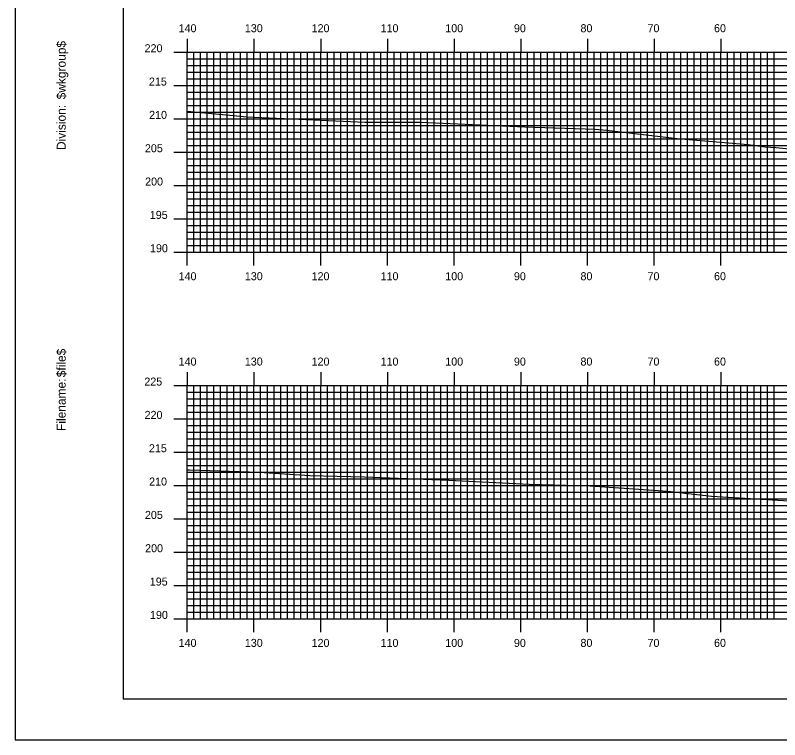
# Model space of a CAD drawing. Extents: x 1805864 to 1806208, y 442591 to 442811.
# Drawn here: x 1805864.4 to 1805979, y 442590.5 to 442699.2 of the extents above; entities that cross this region are included whole.
import ezdxf

# ---------------------------------------------------------------- set-up
doc = ezdxf.new("R2010")
doc.units = 0
for name, color, linetype in [('BORDER', 7, 'Continuous'), ('H_V ANNOTATION', 7, 'Continuous'), ('MAJOR', 7, 'Continuous'), ('MINOR', 7, 'Continuous'), ('PLOT BOUNDARY', 7, 'Continuous'), ('S_Roadway_Centerline', 7, 'Continuous')]:
    doc.layers.add(name, color=color, linetype=linetype)

msp = doc.modelspace()

# ---------------------------------------------------------------- linework, layer by layer
at = {"layer": 'BORDER'}
msp.add_lwpolyline([(1805880.62, 442596.67), (1806200.62, 442596.67), (1806200.62, 442806.67), (1805880.62, 442806.67)], close=True, dxfattribs=at)
at = {"layer": 'MAJOR'}
for p, q in [((1805890.22, 442695.67), (1805890.22, 442693.67)), ((1805900.22, 442695.67), (1805900.22, 442693.67)), ((1805910.22, 442695.67), (1805910.22, 442693.67)), ((1805920.22, 442695.67), (1805920.22, 442693.67)), ((1805930.22, 442695.67), (1805930.22, 442693.67)), ((1805940.22, 442695.67), (1805940.22, 442693.67)), ((1805950.22, 442695.67), (1805950.22, 442693.67)), ((1805960.22, 442695.67), (1805960.22, 442693.67)), ((1805970.22, 442695.67), (1805970.22, 442693.67)), ((1805888.22, 442693.67), (1805890.22, 442693.67)), ((1805890.22, 442693.67), (1806170.22, 442693.67)), ((1805890.22, 442663.67), (1805890.22, 442693.67)), ((1805890.22, 442663.67), (1805890.22, 442693.67)), ((1805890.22, 442693.67), (1806170.22, 442693.67)), ((1805900.22, 442663.67), (1805900.22, 442693.67)), ((1805910.22, 442663.67), (1805910.22, 442693.67)), ((1805920.22, 442663.67), (1805920.22, 442693.67)), ((1805930.22, 442663.67), (1805930.22, 442693.67)), ((1805940.22, 442663.67), (1805940.22, 442693.67)), ((1805950.22, 442663.67), (1805950.22, 442693.67)), ((1805960.22, 442663.67), (1805960.22, 442693.67)), ((1805970.22, 442663.67), (1805970.22, 442693.67)), ((1805888.22, 442688.67), (1805890.22, 442688.67)), ((1805890.22, 442688.67), (1806170.22, 442688.67)), ((1805888.22, 442683.67), (1805890.22, 442683.67)), ((1805890.22, 442683.67), (1806170.22, 442683.67)), ((1805888.22, 442678.67), (1805890.22, 442678.67)), ((1805890.22, 442678.67), (1806170.22, 442678.67)), ((1805888.22, 442673.67), (1805890.22, 442673.67)), ((1805890.22, 442673.67), (1806170.22, 442673.67)), ((1805888.22, 442668.67), (1805890.22, 442668.67)), ((1805890.22, 442668.67), (1806170.22, 442668.67)), ((1805888.22, 442663.67), (1805890.22, 442663.67)), ((1805890.22, 442663.67), (1806170.22, 442663.67)), ((1805890.22, 442663.67), (1806170.22, 442663.67)), ((1805890.22, 442661.66), (1805890.22, 442663.67)), ((1805900.22, 442661.66), (1805900.22, 442663.67)), ((1805910.22, 442661.66), (1805910.22, 442663.67)), ((1805920.22, 442661.66), (1805920.22, 442663.67)), ((1805930.22, 442661.66), (1805930.22, 442663.67)), ((1805940.22, 442661.66), (1805940.22, 442663.67)), ((1805950.22, 442661.66), (1805950.22, 442663.67)), ((1805960.22, 442661.66), (1805960.22, 442663.67)), ((1805970.22, 442661.66), (1805970.22, 442663.67)), ((1805890.22, 442645.67), (1805890.22, 442643.67)), ((1805900.22, 442645.67), (1805900.22, 442643.67)), ((1805910.22, 442645.67), (1805910.22, 442643.67)), ((1805920.22, 442645.67), (1805920.22, 442643.67)), ((1805930.22, 442645.67), (1805930.22, 442643.67)), ((1805940.22, 442645.67), (1805940.22, 442643.67)), ((1805950.22, 442645.67), (1805950.22, 442643.67)), ((1805960.22, 442645.67), (1805960.22, 442643.67)), ((1805970.22, 442645.67), (1805970.22, 442643.67)), ((1805888.22, 442643.67), (1805890.22, 442643.67)), ((1805890.22, 442643.67), (1806170.22, 442643.67)), ((1805890.22, 442608.67), (1805890.22, 442643.67)), ((1805890.22, 442608.67), (1805890.22, 442643.67)), ((1805890.22, 442643.67), (1806170.22, 442643.67)), ((1805900.22, 442608.67), (1805900.22, 442643.67)), ((1805910.22, 442608.67), (1805910.22, 442643.67)), ((1805920.22, 442608.67), (1805920.22, 442643.67)), ((1805930.22, 442608.67), (1805930.22, 442643.67)), ((1805940.22, 442608.67), (1805940.22, 442643.67)), ((1805950.22, 442608.67), (1805950.22, 442643.67)), ((1805960.22, 442608.67), (1805960.22, 442643.67)), ((1805970.22, 442608.67), (1805970.22, 442643.67)), ((1805888.22, 442638.67), (1805890.22, 442638.67)), ((1805890.22, 442638.67), (1806170.22, 442638.67)), ((1805888.22, 442633.67), (1805890.22, 442633.67)), ((1805890.22, 442633.67), (1806170.22, 442633.67)), ((1805888.22, 442628.67), (1805890.22, 442628.67)), ((1805890.22, 442628.67), (1806170.22, 442628.67)), ((1805888.22, 442623.67), (1805890.22, 442623.67)), ((1805890.22, 442623.67), (1806170.22, 442623.67)), ((1805888.22, 442618.67), (1805890.22, 442618.67)), ((1805890.22, 442618.67), (1806170.22, 442618.67)), ((1805888.22, 442613.67), (1805890.22, 442613.67)), ((1805890.22, 442613.67), (1806170.22, 442613.67)), ((1805888.22, 442608.67), (1805890.22, 442608.67)), ((1805890.22, 442608.67), (1806170.22, 442608.67)), ((1805890.22, 442608.67), (1806170.22, 442608.67)), ((1805890.22, 442606.66), (1805890.22, 442608.67)), ((1805900.22, 442606.66), (1805900.22, 442608.67)), ((1805910.22, 442606.66), (1805910.22, 442608.67)), ((1805920.22, 442606.66), (1805920.22, 442608.67)), ((1805930.22, 442606.66), (1805930.22, 442608.67)), ((1805940.22, 442606.66), (1805940.22, 442608.67)), ((1805950.22, 442606.66), (1805950.22, 442608.67)), ((1805960.22, 442606.66), (1805960.22, 442608.67)), ((1805970.22, 442606.66), (1805970.22, 442608.67))]:
    msp.add_line(p, q, dxfattribs=at)
at = {"layer": 'MINOR'}
for p, q in [((1805891.22, 442663.67), (1805891.22, 442693.67)), ((1805892.22, 442663.67), (1805892.22, 442693.67)), ((1805893.22, 442663.67), (1805893.22, 442693.67)), ((1805894.22, 442663.67), (1805894.22, 442693.67)), ((1805895.22, 442663.67), (1805895.22, 442693.67)), ((1805896.22, 442663.67), (1805896.22, 442693.67)), ((1805897.22, 442663.67), (1805897.22, 442693.67)), ((1805898.22, 442663.67), (1805898.22, 442693.67)), ((1805899.22, 442663.67), (1805899.22, 442693.67)), ((1805901.22, 442663.67), (1805901.22, 442693.67)), ((1805902.22, 442663.67), (1805902.22, 442693.67)), ((1805903.22, 442663.67), (1805903.22, 442693.67)), ((1805904.22, 442663.67), (1805904.22, 442693.67)), ((1805905.22, 442663.67), (1805905.22, 442693.67)), ((1805906.22, 442663.67), (1805906.22, 442693.67)), ((1805907.22, 442663.67), (1805907.22, 442693.67)), ((1805908.22, 442663.67), (1805908.22, 442693.67)), ((1805909.22, 442663.67), (1805909.22, 442693.67)), ((1805911.22, 442663.67), (1805911.22, 442693.67)), ((1805912.22, 442663.67), (1805912.22, 442693.67)), ((1805913.22, 442663.67), (1805913.22, 442693.67)), ((1805914.22, 442663.67), (1805914.22, 442693.67)), ((1805915.22, 442663.67), (1805915.22, 442693.67)), ((1805916.22, 442663.67), (1805916.22, 442693.67)), ((1805917.22, 442663.67), (1805917.22, 442693.67)), ((1805918.22, 442663.67), (1805918.22, 442693.67)), ((1805919.22, 442663.67), (1805919.22, 442693.67)), ((1805921.22, 442663.67), (1805921.22, 442693.67)), ((1805922.22, 442663.67), (1805922.22, 442693.67)), ((1805923.22, 442663.67), (1805923.22, 442693.67)), ((1805924.22, 442663.67), (1805924.22, 442693.67)), ((1805925.22, 442663.67), (1805925.22, 442693.67)), ((1805926.22, 442663.67), (1805926.22, 442693.67)), ((1805927.22, 442663.67), (1805927.22, 442693.67)), ((1805928.22, 442663.67), (1805928.22, 442693.67)), ((1805929.22, 442663.67), (1805929.22, 442693.67)), ((1805931.22, 442663.67), (1805931.22, 442693.67)), ((1805932.22, 442663.67), (1805932.22, 442693.67)), ((1805933.22, 442663.67), (1805933.22, 442693.67)), ((1805934.22, 442663.67), (1805934.22, 442693.67)), ((1805935.22, 442663.67), (1805935.22, 442693.67)), ((1805936.22, 442663.67), (1805936.22, 442693.67)), ((1805937.22, 442663.67), (1805937.22, 442693.67)), ((1805938.22, 442663.67), (1805938.22, 442693.67)), ((1805939.22, 442663.67), (1805939.22, 442693.67)), ((1805941.22, 442663.67), (1805941.22, 442693.67)), ((1805942.22, 442663.67), (1805942.22, 442693.67)), ((1805943.22, 442663.67), (1805943.22, 442693.67)), ((1805944.22, 442663.67), (1805944.22, 442693.67)), ((1805945.22, 442663.67), (1805945.22, 442693.67)), ((1805946.22, 442663.67), (1805946.22, 442693.67)), ((1805947.22, 442663.67), (1805947.22, 442693.67)), ((1805948.22, 442663.67), (1805948.22, 442693.67)), ((1805949.22, 442663.67), (1805949.22, 442693.67)), ((1805951.22, 442663.67), (1805951.22, 442693.67)), ((1805952.22, 442663.67), (1805952.22, 442693.67)), ((1805953.22, 442663.67), (1805953.22, 442693.67)), ((1805954.22, 442663.67), (1805954.22, 442693.67)), ((1805955.22, 442663.67), (1805955.22, 442693.67)), ((1805956.22, 442663.67), (1805956.22, 442693.67)), ((1805957.22, 442663.67), (1805957.22, 442693.67)), ((1805958.22, 442663.67), (1805958.22, 442693.67)), ((1805959.22, 442663.67), (1805959.22, 442693.67)), ((1805961.22, 442663.67), (1805961.22, 442693.67)), ((1805962.22, 442663.67), (1805962.22, 442693.67)), ((1805963.22, 442663.67), (1805963.22, 442693.67)), ((1805964.22, 442663.67), (1805964.22, 442693.67)), ((1805965.22, 442663.67), (1805965.22, 442693.67)), ((1805966.22, 442663.67), (1805966.22, 442693.67)), ((1805967.22, 442663.67), (1805967.22, 442693.67)), ((1805968.22, 442663.67), (1805968.22, 442693.67)), ((1805969.22, 442663.67), (1805969.22, 442693.67)), ((1805971.22, 442663.67), (1805971.22, 442693.67)), ((1805972.22, 442663.67), (1805972.22, 442693.67)), ((1805973.22, 442663.67), (1805973.22, 442693.67)), ((1805974.22, 442663.67), (1805974.22, 442693.67)), ((1805975.22, 442663.67), (1805975.22, 442693.67)), ((1805976.22, 442663.67), (1805976.22, 442693.67)), ((1805977.22, 442663.67), (1805977.22, 442693.67)), ((1805978.22, 442663.67), (1805978.22, 442693.67)), ((1805890.22, 442692.67), (1806170.22, 442692.67)), ((1805890.22, 442692.67), (1805892.22, 442692.67)), ((1805890.22, 442691.67), (1806170.22, 442691.67)), ((1805890.22, 442691.67), (1805892.22, 442691.67)), ((1805890.22, 442690.67), (1806170.22, 442690.67)), ((1805890.22, 442690.67), (1805892.22, 442690.67)), ((1805890.22, 442689.67), (1806170.22, 442689.67)), ((1805890.22, 442689.67), (1805892.22, 442689.67)), ((1805890.22, 442687.67), (1806170.22, 442687.67)), ((1805890.22, 442687.67), (1805892.22, 442687.67)), ((1805890.22, 442686.67), (1806170.22, 442686.67)), ((1805890.22, 442686.67), (1805892.22, 442686.67)), ((1805890.22, 442685.67), (1806170.22, 442685.67)), ((1805890.22, 442685.67), (1805892.22, 442685.67)), ((1805890.22, 442684.67), (1806170.22, 442684.67)), ((1805890.22, 442684.67), (1805892.22, 442684.67)), ((1805890.22, 442682.67), (1806170.22, 442682.67)), ((1805890.22, 442682.67), (1805892.22, 442682.67)), ((1805890.22, 442681.67), (1806170.22, 442681.67)), ((1805890.22, 442681.67), (1805892.22, 442681.67)), ((1805890.22, 442680.67), (1806170.22, 442680.67)), ((1805890.22, 442680.67), (1805892.22, 442680.67)), ((1805890.22, 442679.67), (1806170.22, 442679.67)), ((1805890.22, 442679.67), (1805892.22, 442679.67)), ((1805890.22, 442677.67), (1806170.22, 442677.67)), ((1805890.22, 442677.67), (1805892.22, 442677.67)), ((1805890.22, 442676.67), (1806170.22, 442676.67)), ((1805890.22, 442676.67), (1805892.22, 442676.67)), ((1805890.22, 442675.67), (1806170.22, 442675.67)), ((1805890.22, 442675.67), (1805892.22, 442675.67)), ((1805890.22, 442674.67), (1806170.22, 442674.67)), ((1805890.22, 442674.67), (1805892.22, 442674.67)), ((1805890.22, 442672.67), (1806170.22, 442672.67)), ((1805890.22, 442672.67), (1805892.22, 442672.67)), ((1805890.22, 442671.67), (1806170.22, 442671.67)), ((1805890.22, 442671.67), (1805892.22, 442671.67)), ((1805890.22, 442670.67), (1806170.22, 442670.67)), ((1805890.22, 442670.67), (1805892.22, 442670.67)), ((1805890.22, 442669.67), (1806170.22, 442669.67)), ((1805890.22, 442669.67), (1805892.22, 442669.67)), ((1805890.22, 442667.67), (1806170.22, 442667.67)), ((1805890.22, 442667.67), (1805892.22, 442667.67)), ((1805890.22, 442666.67), (1806170.22, 442666.67)), ((1805890.22, 442666.67), (1805892.22, 442666.67)), ((1805890.22, 442665.67), (1806170.22, 442665.67)), ((1805890.22, 442665.67), (1805892.22, 442665.67)), ((1805890.22, 442664.67), (1806170.22, 442664.67)), ((1805890.22, 442664.67), (1805892.22, 442664.67)), ((1805891.22, 442608.67), (1805891.22, 442643.67)), ((1805892.22, 442608.67), (1805892.22, 442643.67)), ((1805893.22, 442608.67), (1805893.22, 442643.67)), ((1805894.22, 442608.67), (1805894.22, 442643.67)), ((1805895.22, 442608.67), (1805895.22, 442643.67)), ((1805896.22, 442608.67), (1805896.22, 442643.67)), ((1805897.22, 442608.67), (1805897.22, 442643.67)), ((1805898.22, 442608.67), (1805898.22, 442643.67)), ((1805899.22, 442608.67), (1805899.22, 442643.67)), ((1805901.22, 442608.67), (1805901.22, 442643.67)), ((1805902.22, 442608.67), (1805902.22, 442643.67)), ((1805903.22, 442608.67), (1805903.22, 442643.67)), ((1805904.22, 442608.67), (1805904.22, 442643.67)), ((1805905.22, 442608.67), (1805905.22, 442643.67)), ((1805906.22, 442608.67), (1805906.22, 442643.67)), ((1805907.22, 442608.67), (1805907.22, 442643.67)), ((1805908.22, 442608.67), (1805908.22, 442643.67)), ((1805909.22, 442608.67), (1805909.22, 442643.67)), ((1805911.22, 442608.67), (1805911.22, 442643.67)), ((1805912.22, 442608.67), (1805912.22, 442643.67)), ((1805913.22, 442608.67), (1805913.22, 442643.67)), ((1805914.22, 442608.67), (1805914.22, 442643.67)), ((1805915.22, 442608.67), (1805915.22, 442643.67)), ((1805916.22, 442608.67), (1805916.22, 442643.67)), ((1805917.22, 442608.67), (1805917.22, 442643.67)), ((1805918.22, 442608.67), (1805918.22, 442643.67)), ((1805919.22, 442608.67), (1805919.22, 442643.67)), ((1805921.22, 442608.67), (1805921.22, 442643.67)), ((1805922.22, 442608.67), (1805922.22, 442643.67)), ((1805923.22, 442608.67), (1805923.22, 442643.67)), ((1805924.22, 442608.67), (1805924.22, 442643.67)), ((1805925.22, 442608.67), (1805925.22, 442643.67)), ((1805926.22, 442608.67), (1805926.22, 442643.67)), ((1805927.22, 442608.67), (1805927.22, 442643.67)), ((1805928.22, 442608.67), (1805928.22, 442643.67)), ((1805929.22, 442608.67), (1805929.22, 442643.67)), ((1805931.22, 442608.67), (1805931.22, 442643.67)), ((1805932.22, 442608.67), (1805932.22, 442643.67)), ((1805933.22, 442608.67), (1805933.22, 442643.67)), ((1805934.22, 442608.67), (1805934.22, 442643.67)), ((1805935.22, 442608.67), (1805935.22, 442643.67)), ((1805936.22, 442608.67), (1805936.22, 442643.67)), ((1805937.22, 442608.67), (1805937.22, 442643.67)), ((1805938.22, 442608.67), (1805938.22, 442643.67)), ((1805939.22, 442608.67), (1805939.22, 442643.67)), ((1805941.22, 442608.67), (1805941.22, 442643.67)), ((1805942.22, 442608.67), (1805942.22, 442643.67)), ((1805943.22, 442608.67), (1805943.22, 442643.67)), ((1805944.22, 442608.67), (1805944.22, 442643.67)), ((1805945.22, 442608.67), (1805945.22, 442643.67)), ((1805946.22, 442608.67), (1805946.22, 442643.67)), ((1805947.22, 442608.67), (1805947.22, 442643.67)), ((1805948.22, 442608.67), (1805948.22, 442643.67)), ((1805949.22, 442608.67), (1805949.22, 442643.67)), ((1805951.22, 442608.67), (1805951.22, 442643.67)), ((1805952.22, 442608.67), (1805952.22, 442643.67)), ((1805953.22, 442608.67), (1805953.22, 442643.67)), ((1805954.22, 442608.67), (1805954.22, 442643.67)), ((1805955.22, 442608.67), (1805955.22, 442643.67)), ((1805956.22, 442608.67), (1805956.22, 442643.67)), ((1805957.22, 442608.67), (1805957.22, 442643.67)), ((1805958.22, 442608.67), (1805958.22, 442643.67)), ((1805959.22, 442608.67), (1805959.22, 442643.67)), ((1805961.22, 442608.67), (1805961.22, 442643.67)), ((1805962.22, 442608.67), (1805962.22, 442643.67)), ((1805963.22, 442608.67), (1805963.22, 442643.67)), ((1805964.22, 442608.67), (1805964.22, 442643.67)), ((1805965.22, 442608.67), (1805965.22, 442643.67)), ((1805966.22, 442608.67), (1805966.22, 442643.67)), ((1805967.22, 442608.67), (1805967.22, 442643.67)), ((1805968.22, 442608.67), (1805968.22, 442643.67)), ((1805969.22, 442608.67), (1805969.22, 442643.67)), ((1805971.22, 442608.67), (1805971.22, 442643.67)), ((1805972.22, 442608.67), (1805972.22, 442643.67)), ((1805973.22, 442608.67), (1805973.22, 442643.67)), ((1805974.22, 442608.67), (1805974.22, 442643.67)), ((1805975.22, 442608.67), (1805975.22, 442643.67)), ((1805976.22, 442608.67), (1805976.22, 442643.67)), ((1805977.22, 442608.67), (1805977.22, 442643.67)), ((1805978.22, 442608.67), (1805978.22, 442643.67)), ((1805890.22, 442642.67), (1806170.22, 442642.67)), ((1805890.22, 442642.67), (1805892.22, 442642.67)), ((1805890.22, 442641.67), (1806170.22, 442641.67)), ((1805890.22, 442641.67), (1805892.22, 442641.67)), ((1805890.22, 442640.67), (1806170.22, 442640.67)), ((1805890.22, 442640.67), (1805892.22, 442640.67)), ((1805890.22, 442639.67), (1806170.22, 442639.67)), ((1805890.22, 442639.67), (1805892.22, 442639.67)), ((1805890.22, 442637.67), (1806170.22, 442637.67)), ((1805890.22, 442637.67), (1805892.22, 442637.67)), ((1805890.22, 442636.67), (1806170.22, 442636.67)), ((1805890.22, 442636.67), (1805892.22, 442636.67)), ((1805890.22, 442635.67), (1806170.22, 442635.67)), ((1805890.22, 442635.67), (1805892.22, 442635.67)), ((1805890.22, 442634.67), (1806170.22, 442634.67)), ((1805890.22, 442634.67), (1805892.22, 442634.67)), ((1805890.22, 442632.67), (1806170.22, 442632.67)), ((1805890.22, 442632.67), (1805892.22, 442632.67)), ((1805890.22, 442631.67), (1806170.22, 442631.67)), ((1805890.22, 442631.67), (1805892.22, 442631.67)), ((1805890.22, 442630.67), (1806170.22, 442630.67)), ((1805890.22, 442630.67), (1805892.22, 442630.67)), ((1805890.22, 442629.67), (1806170.22, 442629.67)), ((1805890.22, 442629.67), (1805892.22, 442629.67)), ((1805890.22, 442627.67), (1806170.22, 442627.67)), ((1805890.22, 442627.67), (1805892.22, 442627.67)), ((1805890.22, 442626.67), (1806170.22, 442626.67)), ((1805890.22, 442626.67), (1805892.22, 442626.67)), ((1805890.22, 442625.67), (1806170.22, 442625.67)), ((1805890.22, 442625.67), (1805892.22, 442625.67)), ((1805890.22, 442624.67), (1806170.22, 442624.67)), ((1805890.22, 442624.67), (1805892.22, 442624.67)), ((1805890.22, 442622.67), (1806170.22, 442622.67)), ((1805890.22, 442622.67), (1805892.22, 442622.67)), ((1805890.22, 442621.67), (1806170.22, 442621.67)), ((1805890.22, 442621.67), (1805892.22, 442621.67)), ((1805890.22, 442620.67), (1806170.22, 442620.67)), ((1805890.22, 442620.67), (1805892.22, 442620.67)), ((1805890.22, 442619.67), (1806170.22, 442619.67)), ((1805890.22, 442619.67), (1805892.22, 442619.67)), ((1805890.22, 442617.67), (1806170.22, 442617.67)), ((1805890.22, 442617.67), (1805892.22, 442617.67)), ((1805890.22, 442616.67), (1806170.22, 442616.67)), ((1805890.22, 442616.67), (1805892.22, 442616.67)), ((1805890.22, 442615.67), (1806170.22, 442615.67)), ((1805890.22, 442615.67), (1805892.22, 442615.67)), ((1805890.22, 442614.67), (1806170.22, 442614.67)), ((1805890.22, 442614.67), (1805892.22, 442614.67)), ((1805890.22, 442612.67), (1806170.22, 442612.67)), ((1805890.22, 442612.67), (1805892.22, 442612.67)), ((1805890.22, 442611.67), (1806170.22, 442611.67)), ((1805890.22, 442611.67), (1805892.22, 442611.67)), ((1805890.22, 442610.67), (1806170.22, 442610.67)), ((1805890.22, 442610.67), (1805892.22, 442610.67)), ((1805890.22, 442609.67), (1806170.22, 442609.67)), ((1805890.22, 442609.67), (1805892.22, 442609.67))]:
    msp.add_line(p, q, dxfattribs=at)
at = {"layer": 'PLOT BOUNDARY'}
msp.add_lwpolyline([(1805864.43, 442590.55), (1806204.43, 442590.55), (1806204.43, 442810.55), (1805864.43, 442810.55)], close=True, dxfattribs=at)
at = {"layer": 'S_Roadway_Centerline'}
for points in [[(1805890.22, 442684.81), (1805899.22, 442683.99), (1805916.89, 442683.2), (1805925.19, 442683.16), (1805940.8, 442682.48), (1805951.36, 442682.13), (1805953.07, 442681.97), (1805963.64, 442680.71), (1805974.31, 442679.81), (1805976.84, 442679.49), (1805978.48, 442679.38), (1805999.99, 442677.25)], [(1805890.22, 442631.03), (1805890.57, 442631.03), (1805901, 442630.66), (1805908.6, 442630.2), (1805916.78, 442629.96), (1805929.43, 442629.47), (1805941.49, 442628.87), (1805950.62, 442628.65), (1805962.28, 442627.83), (1805968.82, 442627.07), (1805982.88, 442626.24)]]:
    msp.add_lwpolyline(points, dxfattribs=at)

# ---------------------------------------------------------------- texts
at = {"layer": 'BORDER'}
for s, p in [('$wkgroup$', (1805871.99, 442686.6)), ('Division:', (1805871.99, 442679)), ('$file$', (1805871.99, 442644.92)), ('Filename:', (1805871.99, 442636.86))]:
    msp.add_text(s, height=1.339, rotation=90, dxfattribs=at).set_placement(p)
at = {"layer": 'H_V ANNOTATION'}
for s, p in [('140', (1805888.92, 442696.67)), ('130', (1805898.85, 442696.67)), ('120', (1805908.86, 442696.67)), ('110', (1805919.2, 442696.67)), ('100', (1805928.9, 442696.67)), ('90', (1805939.19, 442696.67)), ('80', (1805949.17, 442696.67)), ('70', (1805959.22, 442696.67)), ('60', (1805969.19, 442696.67)), ('220', (1805883.82, 442693.67)), ('215', (1805884.47, 442688.67)), ('210', (1805884.5, 442683.67)), ('205', (1805883.87, 442678.67)), ('200', (1805883.9, 442673.67)), ('195', (1805884.6, 442668.67)), ('190', (1805884.63, 442663.67)), ('140', (1805888.92, 442659.47)), ('130', (1805898.85, 442659.47)), ('120', (1805908.86, 442659.47)), ('110', (1805919.2, 442659.47)), ('100', (1805928.9, 442659.47)), ('90', (1805939.19, 442659.47)), ('80', (1805949.17, 442659.47)), ('70', (1805959.22, 442659.47)), ('60', (1805969.19, 442659.47)), ('140', (1805888.92, 442646.67)), ('130', (1805898.85, 442646.67)), ('120', (1805908.86, 442646.67)), ('110', (1805919.2, 442646.67)), ('100', (1805928.9, 442646.67)), ('90', (1805939.19, 442646.67)), ('80', (1805949.17, 442646.67)), ('70', (1805959.22, 442646.67)), ('60', (1805969.19, 442646.67)), ('225', (1805883.78, 442643.67)), ('220', (1805883.82, 442638.67)), ('215', (1805884.47, 442633.67)), ('210', (1805884.5, 442628.67)), ('205', (1805883.87, 442623.67)), ('200', (1805883.9, 442618.67)), ('195', (1805884.6, 442613.67)), ('190', (1805884.63, 442608.67)), ('140', (1805888.92, 442604.47)), ('130', (1805898.85, 442604.47)), ('120', (1805908.86, 442604.47)), ('110', (1805919.2, 442604.47)), ('100', (1805928.9, 442604.47)), ('90', (1805939.19, 442604.47)), ('80', (1805949.17, 442604.47)), ('70', (1805959.22, 442604.47)), ('60', (1805969.19, 442604.47))]:
    msp.add_text(s, height=1.2, dxfattribs=at).set_placement(p)
at = {"layer": 'MAJOR'}
for p in [(1805890.21, 442663.67), (1805890.21, 442608.67)]:
    msp.add_text('-', height=0.012, dxfattribs=at).set_placement(p)

doc.saveas('drawing.dxf')
